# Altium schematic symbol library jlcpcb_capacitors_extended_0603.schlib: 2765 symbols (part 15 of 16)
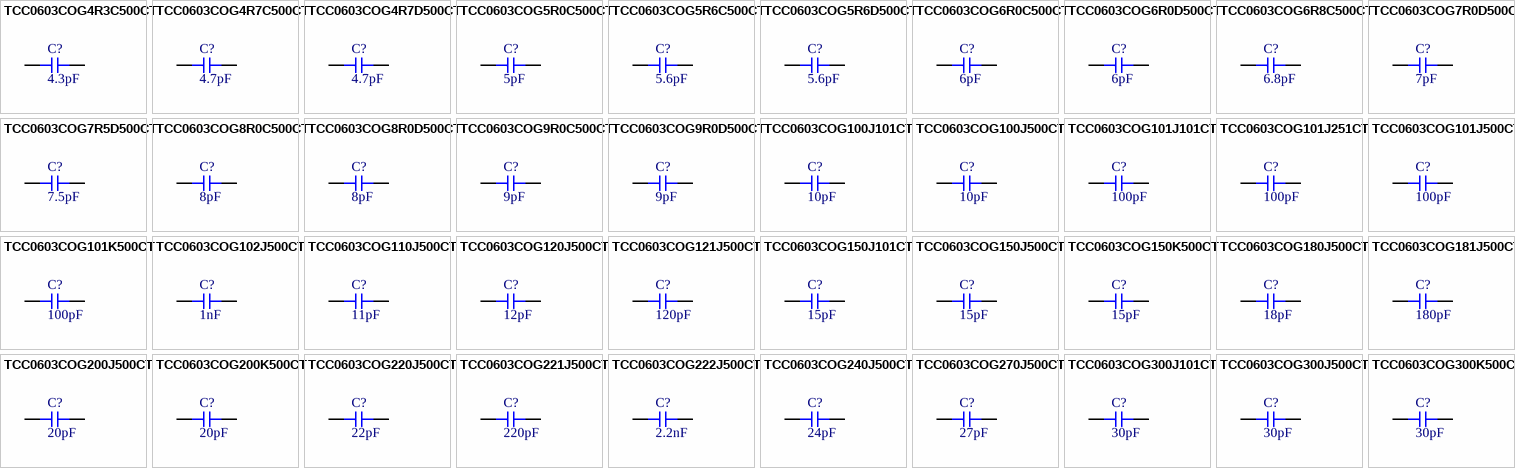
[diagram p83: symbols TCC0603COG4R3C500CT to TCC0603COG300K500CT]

## TCC0603COG4R7C500CT
designator C?  Capacitance: 4.7pF  (hidden comment: *)
Capacitor, Ceramic (MLCC), 4.7pF, ±0.25pF, 50V, C0G, ±0.25pF, SMD 0603; Manufacturer: CCTC; Manufacturer Part Number: TCC0603COG4R7C500CT
footprint CAP-0603 (0603 (1608M) Capacitor)
pins: 1, 2

## TCC0603COG4R7D500CT
designator C?  Capacitance: 4.7pF  (hidden comment: *)
Capacitor, Ceramic (MLCC), 4.7pF, ±0.5pF, 50V, C0G, ±0.5pF, SMD 0603; Manufacturer: CCTC; Manufacturer Part Number: TCC0603COG4R7D500CT
footprint CAP-0603 (0603 (1608M) Capacitor)
pins: 1, 2

## TCC0603COG5R0C500CT
designator C?  Capacitance: 5pF  (hidden comment: *)
Capacitor, Ceramic (MLCC), 5pF, ±0.25pF, 50V, C0G, ±0.25pF, SMD 0603; Manufacturer: CCTC; Manufacturer Part Number: TCC0603COG5R0C500CT
footprint CAP-0603 (0603 (1608M) Capacitor)
pins: 1, 2

## TCC0603COG5R6C500CT
designator C?  Capacitance: 5.6pF  (hidden comment: *)
Capacitor, Ceramic (MLCC), 5.6pF, ±0.25pF, 50V, C0G, ±0.25pF, SMD 0603; Manufacturer: CCTC; Manufacturer Part Number: TCC0603COG5R6C500CT
footprint CAP-0603 (0603 (1608M) Capacitor)
pins: 1, 2

## TCC0603COG5R6D500CT
designator C?  Capacitance: 5.6pF  (hidden comment: *)
Capacitor, Ceramic (MLCC), 5.6pF, ±0.5pF, 50V, C0G, ±0.5pF, SMD 0603; Manufacturer: CCTC; Manufacturer Part Number: TCC0603COG5R6D500CT
footprint CAP-0603 (0603 (1608M) Capacitor)
pins: 1, 2

## TCC0603COG6R0C500CT
designator C?  Capacitance: 6pF  (hidden comment: *)
Capacitor, Ceramic (MLCC), 6pF, ±0.25pF, 50V, C0G, ±0.25pF, SMD 0603; Manufacturer: CCTC; Manufacturer Part Number: TCC0603COG6R0C500CT
footprint CAP-0603 (0603 (1608M) Capacitor)
pins: 1, 2

## TCC0603COG6R0D500CT
designator C?  Capacitance: 6pF  (hidden comment: *)
Capacitor, Ceramic (MLCC), 6pF, ±0.5pF, 50V, C0G, ±0.5pF, SMD 0603; Manufacturer: CCTC; Manufacturer Part Number: TCC0603COG6R0D500CT
footprint CAP-0603 (0603 (1608M) Capacitor)
pins: 1, 2

## TCC0603COG6R8C500CT
designator C?  Capacitance: 6.8pF  (hidden comment: *)
Capacitor, Ceramic (MLCC), 6.8pF, ±0.25pF, 50V, C0G, ±0.25pF, SMD 0603; Manufacturer: CCTC; Manufacturer Part Number: TCC0603COG6R8C500CT
footprint CAP-0603 (0603 (1608M) Capacitor)
pins: 1, 2

## TCC0603COG7R0D500CT
designator C?  Capacitance: 7pF  (hidden comment: *)
Capacitor, Ceramic (MLCC), 7pF, ±0.5pF, 50V, C0G, ±0.5pF, SMD 0603; Manufacturer: CCTC; Manufacturer Part Number: TCC0603COG7R0D500CT
footprint CAP-0603 (0603 (1608M) Capacitor)
pins: 1, 2

## TCC0603COG7R5D500CT
designator C?  Capacitance: 7.5pF  (hidden comment: *)
Capacitor, Ceramic (MLCC), 7.5pF, ±0.5pF, 50V, C0G, ±0.5pF, SMD 0603; Manufacturer: CCTC; Manufacturer Part Number: TCC0603COG7R5D500CT
footprint CAP-0603 (0603 (1608M) Capacitor)
pins: 1, 2

## TCC0603COG8R0C500CT
designator C?  Capacitance: 8pF  (hidden comment: *)
Capacitor, Ceramic (MLCC), 8pF, ±0.25pF, 50V, C0G, ±0.25pF, SMD 0603; Manufacturer: CCTC; Manufacturer Part Number: TCC0603COG8R0C500CT
footprint CAP-0603 (0603 (1608M) Capacitor)
pins: 1, 2

## TCC0603COG8R0D500CT
designator C?  Capacitance: 8pF  (hidden comment: *)
Capacitor, Ceramic (MLCC), 8pF, ±0.5pF, 50V, C0G, ±0.5pF, SMD 0603; Manufacturer: CCTC; Manufacturer Part Number: TCC0603COG8R0D500CT
footprint CAP-0603 (0603 (1608M) Capacitor)
pins: 1, 2

## TCC0603COG9R0C500CT
designator C?  Capacitance: 9pF  (hidden comment: *)
Capacitor, Ceramic (MLCC), 9pF, ±0.25pF, 50V, C0G, ±0.25pF, SMD 0603; Manufacturer: CCTC; Manufacturer Part Number: TCC0603COG9R0C500CT
footprint CAP-0603 (0603 (1608M) Capacitor)
pins: 1, 2

## TCC0603COG9R0D500CT
designator C?  Capacitance: 9pF  (hidden comment: *)
Capacitor, Ceramic (MLCC), 9pF, ±0.5pF, 50V, C0G, ±0.5pF, SMD 0603; Manufacturer: CCTC; Manufacturer Part Number: TCC0603COG9R0D500CT
footprint CAP-0603 (0603 (1608M) Capacitor)
pins: 1, 2

## TCC0603COG100J101CT
designator C?  Capacitance: 10pF  (hidden comment: *)
Capacitor, Ceramic (MLCC), 10pF, ±5%, 100V, C0G, ±5%, SMD 0603; Manufacturer: CCTC; Manufacturer Part Number: TCC0603COG100J101CT
footprint CAP-0603 (0603 (1608M) Capacitor)
pins: 1, 2

## TCC0603COG100J500CT
designator C?  Capacitance: 10pF  (hidden comment: *)
Capacitor, Ceramic (MLCC), 10pF, ±5%, 50V, C0G, ±5%, SMD 0603; Manufacturer: CCTC; Manufacturer Part Number: TCC0603COG100J500CT
footprint CAP-0603 (0603 (1608M) Capacitor)
pins: 1, 2

## TCC0603COG101J101CT
designator C?  Capacitance: 100pF  (hidden comment: *)
Capacitor, Ceramic (MLCC), 100pF, ±5%, 100V, C0G, ±5%, SMD 0603; Manufacturer: CCTC; Manufacturer Part Number: TCC0603COG101J101CT
footprint CAP-0603 (0603 (1608M) Capacitor)
pins: 1, 2

## TCC0603COG101J251CT
designator C?  Capacitance: 100pF  (hidden comment: *)
Capacitor, Ceramic (MLCC), 100pF, ±5%, 250V, C0G, ±5%, SMD 0603; Manufacturer: CCTC; Manufacturer Part Number: TCC0603COG101J251CT
footprint CAP-0603 (0603 (1608M) Capacitor)
pins: 1, 2

## TCC0603COG101J500CT
designator C?  Capacitance: 100pF  (hidden comment: *)
Capacitor, Ceramic (MLCC), 100pF, ±5%, 50V, C0G, ±5%, SMD 0603; Manufacturer: CCTC; Manufacturer Part Number: TCC0603COG101J500CT
footprint CAP-0603 (0603 (1608M) Capacitor)
pins: 1, 2

## TCC0603COG101K500CT
designator C?  Capacitance: 100pF  (hidden comment: *)
Capacitor, Ceramic (MLCC), 100pF, ±10%, 50V, C0G, ±10%, SMD 0603; Manufacturer: CCTC; Manufacturer Part Number: TCC0603COG101K500CT
footprint CAP-0603 (0603 (1608M) Capacitor)
pins: 1, 2

## TCC0603COG102J500CT
designator C?  Capacitance: 1nF  (hidden comment: *)
Capacitor, Ceramic (MLCC), 1nF, ±5%, 50V, C0G, ±5%, SMD 0603; Manufacturer: CCTC; Manufacturer Part Number: TCC0603COG102J500CT
footprint CAP-0603 (0603 (1608M) Capacitor)
pins: 1, 2

## TCC0603COG110J500CT
designator C?  Capacitance: 11pF  (hidden comment: *)
Capacitor, Ceramic (MLCC), 11pF, ±5%, 50V, C0G, ±5%, SMD 0603; Manufacturer: CCTC; Manufacturer Part Number: TCC0603COG110J500CT
footprint CAP-0603 (0603 (1608M) Capacitor)
pins: 1, 2

## TCC0603COG120J500CT
designator C?  Capacitance: 12pF  (hidden comment: *)
Capacitor, Ceramic (MLCC), 12pF, ±5%, 50V, C0G, ±5%, SMD 0603; Manufacturer: CCTC; Manufacturer Part Number: TCC0603COG120J500CT
footprint CAP-0603 (0603 (1608M) Capacitor)
pins: 1, 2

## TCC0603COG121J500CT
designator C?  Capacitance: 120pF  (hidden comment: *)
Capacitor, Ceramic (MLCC), 120pF, ±5%, 50V, C0G, ±5%, SMD 0603; Manufacturer: CCTC; Manufacturer Part Number: TCC0603COG121J500CT
footprint CAP-0603 (0603 (1608M) Capacitor)
pins: 1, 2

## TCC0603COG150J101CT
designator C?  Capacitance: 15pF  (hidden comment: *)
Capacitor, Ceramic (MLCC), 15pF, ±5%, 100V, C0G, ±5%, SMD 0603; Manufacturer: CCTC; Manufacturer Part Number: TCC0603COG150J101CT
footprint CAP-0603 (0603 (1608M) Capacitor)
pins: 1, 2

## TCC0603COG150J500CT
designator C?  Capacitance: 15pF  (hidden comment: *)
Capacitor, Ceramic (MLCC), 15pF, ±5%, 50V, C0G, ±5%, SMD 0603; Manufacturer: CCTC; Manufacturer Part Number: TCC0603COG150J500CT
footprint CAP-0603 (0603 (1608M) Capacitor)
pins: 1, 2

## TCC0603COG150K500CT
designator C?  Capacitance: 15pF  (hidden comment: *)
Capacitor, Ceramic (MLCC), 15pF, ±10%, 50V, C0G, ±10%, SMD 0603; Manufacturer: CCTC; Manufacturer Part Number: TCC0603COG150K500CT
footprint CAP-0603 (0603 (1608M) Capacitor)
pins: 1, 2

## TCC0603COG180J500CT
designator C?  Capacitance: 18pF  (hidden comment: *)
Capacitor, Ceramic (MLCC), 18pF, ±5%, 50V, C0G, ±5%, SMD 0603; Manufacturer: CCTC; Manufacturer Part Number: TCC0603COG180J500CT
footprint CAP-0603 (0603 (1608M) Capacitor)
pins: 1, 2

## TCC0603COG181J500CT
designator C?  Capacitance: 180pF  (hidden comment: *)
Capacitor, Ceramic (MLCC), 180pF, ±5%, 50V, C0G, ±5%, SMD 0603; Manufacturer: CCTC; Manufacturer Part Number: TCC0603COG181J500CT
footprint CAP-0603 (0603 (1608M) Capacitor)
pins: 1, 2

## TCC0603COG200J500CT
designator C?  Capacitance: 20pF  (hidden comment: *)
Capacitor, Ceramic (MLCC), 20pF, ±5%, 50V, C0G, ±5%, SMD 0603; Manufacturer: CCTC; Manufacturer Part Number: TCC0603COG200J500CT
footprint CAP-0603 (0603 (1608M) Capacitor)
pins: 1, 2

## TCC0603COG200K500CT
designator C?  Capacitance: 20pF  (hidden comment: *)
Capacitor, Ceramic (MLCC), 20pF, ±10%, 50V, C0G, ±10%, SMD 0603; Manufacturer: CCTC; Manufacturer Part Number: TCC0603COG200K500CT
footprint CAP-0603 (0603 (1608M) Capacitor)
pins: 1, 2

## TCC0603COG220J500CT
designator C?  Capacitance: 22pF  (hidden comment: *)
Capacitor, Ceramic (MLCC), 22pF, ±5%, 50V, C0G, ±5%, SMD 0603; Manufacturer: CCTC; Manufacturer Part Number: TCC0603COG220J500CT
footprint CAP-0603 (0603 (1608M) Capacitor)
pins: 1, 2

## TCC0603COG221J500CT
designator C?  Capacitance: 220pF  (hidden comment: *)
Capacitor, Ceramic (MLCC), 220pF, ±5%, 50V, C0G, ±5%, SMD 0603; Manufacturer: CCTC; Manufacturer Part Number: TCC0603COG221J500CT
footprint CAP-0603 (0603 (1608M) Capacitor)
pins: 1, 2

## TCC0603COG222J500CT
designator C?  Capacitance: 2.2nF  (hidden comment: *)
Capacitor, Ceramic (MLCC), 2.2nF, ±5%, 50V, C0G, ±5%, SMD 0603; Manufacturer: CCTC; Manufacturer Part Number: TCC0603COG222J500CT
footprint CAP-0603 (0603 (1608M) Capacitor)
pins: 1, 2

## TCC0603COG240J500CT
designator C?  Capacitance: 24pF  (hidden comment: *)
Capacitor, Ceramic (MLCC), 24pF, ±5%, 50V, C0G, ±5%, SMD 0603; Manufacturer: CCTC; Manufacturer Part Number: TCC0603COG240J500CT
footprint CAP-0603 (0603 (1608M) Capacitor)
pins: 1, 2

## TCC0603COG270J500CT
designator C?  Capacitance: 27pF  (hidden comment: *)
Capacitor, Ceramic (MLCC), 27pF, ±5%, 50V, C0G, ±5%, SMD 0603; Manufacturer: CCTC; Manufacturer Part Number: TCC0603COG270J500CT
footprint CAP-0603 (0603 (1608M) Capacitor)
pins: 1, 2

## TCC0603COG300J101CT
designator C?  Capacitance: 30pF  (hidden comment: *)
Capacitor, Ceramic (MLCC), 30pF, ±5%, 100V, C0G, ±5%, SMD 0603; Manufacturer: CCTC; Manufacturer Part Number: TCC0603COG300J101CT
footprint CAP-0603 (0603 (1608M) Capacitor)
pins: 1, 2

## TCC0603COG300J500CT
designator C?  Capacitance: 30pF  (hidden comment: *)
Capacitor, Ceramic (MLCC), 30pF, ±5%, 50V, C0G, ±5%, SMD 0603; Manufacturer: CCTC; Manufacturer Part Number: TCC0603COG300J500CT
footprint CAP-0603 (0603 (1608M) Capacitor)
pins: 1, 2

## TCC0603COG300K500CT
designator C?  Capacitance: 30pF  (hidden comment: *)
Capacitor, Ceramic (MLCC), 30pF, ±10%, 50V, C0G, ±10%, SMD 0603; Manufacturer: CCTC; Manufacturer Part Number: TCC0603COG300K500CT
footprint CAP-0603 (0603 (1608M) Capacitor)
pins: 1, 2

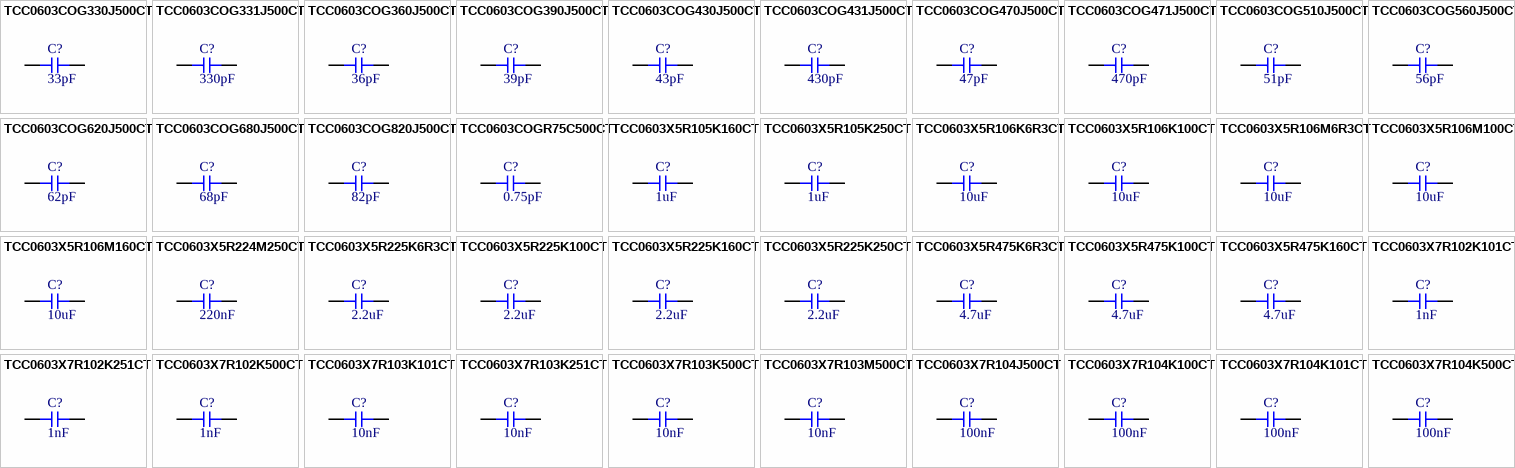
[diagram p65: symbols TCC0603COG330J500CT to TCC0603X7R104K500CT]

## TCC0603COG330J500CT
designator C?  Capacitance: 33pF  (hidden comment: *)
Capacitor, Ceramic (MLCC), 33pF, ±5%, 50V, C0G, ±5%, SMD 0603; Manufacturer: CCTC; Manufacturer Part Number: TCC0603COG330J500CT
footprint CAP-0603 (0603 (1608M) Capacitor)
pins: 1, 2

## TCC0603COG331J500CT
designator C?  Capacitance: 330pF  (hidden comment: *)
Capacitor, Ceramic (MLCC), 330pF, ±5%, 50V, C0G, ±5%, SMD 0603; Manufacturer: CCTC; Manufacturer Part Number: TCC0603COG331J500CT
footprint CAP-0603 (0603 (1608M) Capacitor)
pins: 1, 2

## TCC0603COG360J500CT
designator C?  Capacitance: 36pF  (hidden comment: *)
Capacitor, Ceramic (MLCC), 36pF, ±5%, 50V, C0G, ±5%, SMD 0603; Manufacturer: CCTC; Manufacturer Part Number: TCC0603COG360J500CT
footprint CAP-0603 (0603 (1608M) Capacitor)
pins: 1, 2

## TCC0603COG390J500CT
designator C?  Capacitance: 39pF  (hidden comment: *)
Capacitor, Ceramic (MLCC), 39pF, ±5%, 50V, C0G, ±5%, SMD 0603; Manufacturer: CCTC; Manufacturer Part Number: TCC0603COG390J500CT
footprint CAP-0603 (0603 (1608M) Capacitor)
pins: 1, 2

## TCC0603COG430J500CT
designator C?  Capacitance: 43pF  (hidden comment: *)
Capacitor, Ceramic (MLCC), 43pF, ±5%, 50V, C0G, ±5%, SMD 0603; Manufacturer: CCTC; Manufacturer Part Number: TCC0603COG430J500CT
footprint CAP-0603 (0603 (1608M) Capacitor)
pins: 1, 2

## TCC0603COG431J500CT
designator C?  Capacitance: 430pF  (hidden comment: *)
Capacitor, Ceramic (MLCC), 430pF, ±5%, 50V, C0G, ±5%, SMD 0603; Manufacturer: CCTC; Manufacturer Part Number: TCC0603COG431J500CT
footprint CAP-0603 (0603 (1608M) Capacitor)
pins: 1, 2

## TCC0603COG470J500CT
designator C?  Capacitance: 47pF  (hidden comment: *)
Capacitor, Ceramic (MLCC), 47pF, ±5%, 50V, C0G, ±5%, SMD 0603; Manufacturer: CCTC; Manufacturer Part Number: TCC0603COG470J500CT
footprint CAP-0603 (0603 (1608M) Capacitor)
pins: 1, 2

## TCC0603COG471J500CT
designator C?  Capacitance: 470pF  (hidden comment: *)
Capacitor, Ceramic (MLCC), 470pF, ±5%, 50V, C0G, ±5%, SMD 0603; Manufacturer: CCTC; Manufacturer Part Number: TCC0603COG471J500CT
footprint CAP-0603 (0603 (1608M) Capacitor)
pins: 1, 2

## TCC0603COG510J500CT
designator C?  Capacitance: 51pF  (hidden comment: *)
Capacitor, Ceramic (MLCC), 51pF, ±5%, 50V, C0G, ±5%, SMD 0603; Manufacturer: CCTC; Manufacturer Part Number: TCC0603COG510J500CT
footprint CAP-0603 (0603 (1608M) Capacitor)
pins: 1, 2

## TCC0603COG560J500CT
designator C?  Capacitance: 56pF  (hidden comment: *)
Capacitor, Ceramic (MLCC), 56pF, ±5%, 50V, C0G, ±5%, SMD 0603; Manufacturer: CCTC; Manufacturer Part Number: TCC0603COG560J500CT
footprint CAP-0603 (0603 (1608M) Capacitor)
pins: 1, 2

## TCC0603COG620J500CT
designator C?  Capacitance: 62pF  (hidden comment: *)
Capacitor, Ceramic (MLCC), 62pF, ±5%, 50V, C0G, ±5%, SMD 0603; Manufacturer: CCTC; Manufacturer Part Number: TCC0603COG620J500CT
footprint CAP-0603 (0603 (1608M) Capacitor)
pins: 1, 2

## TCC0603COG680J500CT
designator C?  Capacitance: 68pF  (hidden comment: *)
Capacitor, Ceramic (MLCC), 68pF, ±5%, 50V, C0G, ±5%, SMD 0603; Manufacturer: CCTC; Manufacturer Part Number: TCC0603COG680J500CT
footprint CAP-0603 (0603 (1608M) Capacitor)
pins: 1, 2

## TCC0603COG820J500CT
designator C?  Capacitance: 82pF  (hidden comment: *)
Capacitor, Ceramic (MLCC), 82pF, ±5%, 50V, C0G, ±5%, SMD 0603; Manufacturer: CCTC; Manufacturer Part Number: TCC0603COG820J500CT
footprint CAP-0603 (0603 (1608M) Capacitor)
pins: 1, 2

## TCC0603COGR75C500CT
designator C?  Capacitance: 0.75pF  (hidden comment: *)
Capacitor, Ceramic (MLCC), 0.75pF, ±0.25pF, 50V, C0G, ±0.25pF, SMD 0603; Manufacturer: CCTC; Manufacturer Part Number: TCC0603COGR75C500CT
footprint CAP-0603 (0603 (1608M) Capacitor)
pins: 1, 2

## TCC0603X5R105K160CT
designator C?  Capacitance: 1uF  (hidden comment: *)
Capacitor, Ceramic (MLCC), 1uF, ±10%, 16V, X5R, ±10%, SMD 0603; Manufacturer: CCTC; Manufacturer Part Number: TCC0603X5R105K160CT
footprint CAP-0603 (0603 (1608M) Capacitor)
pins: 1, 2

## TCC0603X5R105K250CT
designator C?  Capacitance: 1uF  (hidden comment: *)
Capacitor, Ceramic (MLCC), 1uF, ±10%, 25V, X5R, ±10%, SMD 0603; Manufacturer: CCTC; Manufacturer Part Number: TCC0603X5R105K250CT
footprint CAP-0603 (0603 (1608M) Capacitor)
pins: 1, 2

## TCC0603X5R106K6R3CT
designator C?  Capacitance: 10uF  (hidden comment: *)
Capacitor, Ceramic (MLCC), 10uF, ±10%, 6.3V, X5R, ±10%, SMD 0603; Manufacturer: CCTC; Manufacturer Part Number: TCC0603X5R106K6R3CT
footprint CAP-0603 (0603 (1608M) Capacitor)
pins: 1, 2

## TCC0603X5R106K100CT
designator C?  Capacitance: 10uF  (hidden comment: *)
Capacitor, Ceramic (MLCC), 10uF, ±10%, 10V, X5R, ±10%, SMD 0603; Manufacturer: CCTC; Manufacturer Part Number: TCC0603X5R106K100CT
footprint CAP-0603 (0603 (1608M) Capacitor)
pins: 1, 2

## TCC0603X5R106M6R3CT
designator C?  Capacitance: 10uF  (hidden comment: *)
Capacitor, Ceramic (MLCC), 10uF, ±20%, 6.3V, X5R, ±20%, SMD 0603; Manufacturer: CCTC; Manufacturer Part Number: TCC0603X5R106M6R3CT
footprint CAP-0603 (0603 (1608M) Capacitor)
pins: 1, 2

## TCC0603X5R106M100CT
designator C?  Capacitance: 10uF  (hidden comment: *)
Capacitor, Ceramic (MLCC), 10uF, ±20%, 10V, X5R, ±20%, SMD 0603; Manufacturer: CCTC; Manufacturer Part Number: TCC0603X5R106M100CT
footprint CAP-0603 (0603 (1608M) Capacitor)
pins: 1, 2

## TCC0603X5R106M160CT
designator C?  Capacitance: 10uF  (hidden comment: *)
Capacitor, Ceramic (MLCC), 10uF, ±20%, 16V, X5R, ±20%, SMD 0603; Manufacturer: CCTC; Manufacturer Part Number: TCC0603X5R106M160CT
footprint CAP-0603 (0603 (1608M) Capacitor)
pins: 1, 2

## TCC0603X5R224M250CT
designator C?  Capacitance: 220nF  (hidden comment: *)
Capacitor, Ceramic (MLCC), 220nF, ±20%, 25V, X5R, ±20%, SMD 0603; Manufacturer: CCTC; Manufacturer Part Number: TCC0603X5R224M250CT
footprint CAP-0603 (0603 (1608M) Capacitor)
pins: 1, 2

## TCC0603X5R225K6R3CT
designator C?  Capacitance: 2.2uF  (hidden comment: *)
Capacitor, Ceramic (MLCC), 2.2uF, ±10%, 6.3V, X5R, ±10%, SMD 0603; Manufacturer: CCTC; Manufacturer Part Number: TCC0603X5R225K6R3CT
footprint CAP-0603 (0603 (1608M) Capacitor)
pins: 1, 2

## TCC0603X5R225K100CT
designator C?  Capacitance: 2.2uF  (hidden comment: *)
Capacitor, Ceramic (MLCC), 2.2uF, ±10%, 10V, X5R, ±10%, SMD 0603; Manufacturer: CCTC; Manufacturer Part Number: TCC0603X5R225K100CT
footprint CAP-0603 (0603 (1608M) Capacitor)
pins: 1, 2

## TCC0603X5R225K160CT
designator C?  Capacitance: 2.2uF  (hidden comment: *)
Capacitor, Ceramic (MLCC), 2.2uF, ±10%, 16V, X5R, ±10%, SMD 0603; Manufacturer: CCTC; Manufacturer Part Number: TCC0603X5R225K160CT
footprint CAP-0603 (0603 (1608M) Capacitor)
pins: 1, 2

## TCC0603X5R225K250CT
designator C?  Capacitance: 2.2uF  (hidden comment: *)
Capacitor, Ceramic (MLCC), 2.2uF, ±10%, 25V, X5R, ±10%, SMD 0603; Manufacturer: CCTC; Manufacturer Part Number: TCC0603X5R225K250CT
footprint CAP-0603 (0603 (1608M) Capacitor)
pins: 1, 2

## TCC0603X5R475K6R3CT
designator C?  Capacitance: 4.7uF  (hidden comment: *)
Capacitor, Ceramic (MLCC), 4.7uF, ±10%, 6.3V, X5R, ±10%, SMD 0603; Manufacturer: CCTC; Manufacturer Part Number: TCC0603X5R475K6R3CT
footprint CAP-0603 (0603 (1608M) Capacitor)
pins: 1, 2

## TCC0603X5R475K100CT
designator C?  Capacitance: 4.7uF  (hidden comment: *)
Capacitor, Ceramic (MLCC), 4.7uF, ±10%, 10V, X5R, ±10%, SMD 0603; Manufacturer: CCTC; Manufacturer Part Number: TCC0603X5R475K100CT
footprint CAP-0603 (0603 (1608M) Capacitor)
pins: 1, 2

## TCC0603X5R475K160CT
designator C?  Capacitance: 4.7uF  (hidden comment: *)
Capacitor, Ceramic (MLCC), 4.7uF, ±10%, 16V, X5R, ±10%, SMD 0603; Manufacturer: CCTC; Manufacturer Part Number: TCC0603X5R475K160CT
footprint CAP-0603 (0603 (1608M) Capacitor)
pins: 1, 2

## TCC0603X7R102K101CT
designator C?  Capacitance: 1nF  (hidden comment: *)
Capacitor, Ceramic (MLCC), 1nF, ±10%, 100V, X7R, ±10%, SMD 0603; Manufacturer: CCTC; Manufacturer Part Number: TCC0603X7R102K101CT
footprint CAP-0603 (0603 (1608M) Capacitor)
pins: 1, 2

## TCC0603X7R102K251CT
designator C?  Capacitance: 1nF  (hidden comment: *)
Capacitor, Ceramic (MLCC), 1nF, ±10%, 250V, X7R, ±10%, SMD 0603; Manufacturer: CCTC; Manufacturer Part Number: TCC0603X7R102K251CT
footprint CAP-0603 (0603 (1608M) Capacitor)
pins: 1, 2

## TCC0603X7R102K500CT
designator C?  Capacitance: 1nF  (hidden comment: *)
Capacitor, Ceramic (MLCC), 1nF, ±10%, 50V, X7R, ±10%, SMD 0603; Manufacturer: CCTC; Manufacturer Part Number: TCC0603X7R102K500CT
footprint CAP-0603 (0603 (1608M) Capacitor)
pins: 1, 2

## TCC0603X7R103K101CT
designator C?  Capacitance: 10nF  (hidden comment: *)
Capacitor, Ceramic (MLCC), 10nF, ±10%, 100V, X7R, ±10%, SMD 0603; Manufacturer: CCTC; Manufacturer Part Number: TCC0603X7R103K101CT
footprint CAP-0603 (0603 (1608M) Capacitor)
pins: 1, 2

## TCC0603X7R103K251CT
designator C?  Capacitance: 10nF  (hidden comment: *)
Capacitor, Ceramic (MLCC), 10nF, ±10%, 250V, X7R, ±10%, SMD 0603; Manufacturer: CCTC; Manufacturer Part Number: TCC0603X7R103K251CT
footprint CAP-0603 (0603 (1608M) Capacitor)
pins: 1, 2

## TCC0603X7R103K500CT
designator C?  Capacitance: 10nF  (hidden comment: *)
Capacitor, Ceramic (MLCC), 10nF, ±10%, 50V, X7R, ±10%, SMD 0603; Manufacturer: CCTC; Manufacturer Part Number: TCC0603X7R103K500CT
footprint CAP-0603 (0603 (1608M) Capacitor)
pins: 1, 2

## TCC0603X7R103M500CT
designator C?  Capacitance: 10nF  (hidden comment: *)
Capacitor, Ceramic (MLCC), 10nF, ±20%, 50V, X7R, ±20%, SMD 0603; Manufacturer: CCTC; Manufacturer Part Number: TCC0603X7R103M500CT
footprint CAP-0603 (0603 (1608M) Capacitor)
pins: 1, 2

## TCC0603X7R104J500CT
designator C?  Capacitance: 100nF  (hidden comment: *)
Capacitor, Ceramic (MLCC), 100nF, ±5%, 50V, X7R, ±5%, SMD 0603; Manufacturer: CCTC; Manufacturer Part Number: TCC0603X7R104J500CT
footprint CAP-0603 (0603 (1608M) Capacitor)
pins: 1, 2

## TCC0603X7R104K100CT
designator C?  Capacitance: 100nF  (hidden comment: *)
Capacitor, Ceramic (MLCC), 100nF, ±10%, 10V, X7R, ±10%, SMD 0603; Manufacturer: CCTC; Manufacturer Part Number: TCC0603X7R104K100CT
footprint CAP-0603 (0603 (1608M) Capacitor)
pins: 1, 2

## TCC0603X7R104K101CT
designator C?  Capacitance: 100nF  (hidden comment: *)
Capacitor, Ceramic (MLCC), 100nF, ±10%, 100V, X7R, ±10%, SMD 0603; Manufacturer: CCTC; Manufacturer Part Number: TCC0603X7R104K101CT
footprint CAP-0603 (0603 (1608M) Capacitor)
pins: 1, 2

## TCC0603X7R104K500CT
designator C?  Capacitance: 100nF  (hidden comment: *)
Capacitor, Ceramic (MLCC), 100nF, ±10%, 50V, X7R, ±10%, SMD 0603; Manufacturer: CCTC; Manufacturer Part Number: TCC0603X7R104K500CT
footprint CAP-0603 (0603 (1608M) Capacitor)
pins: 1, 2

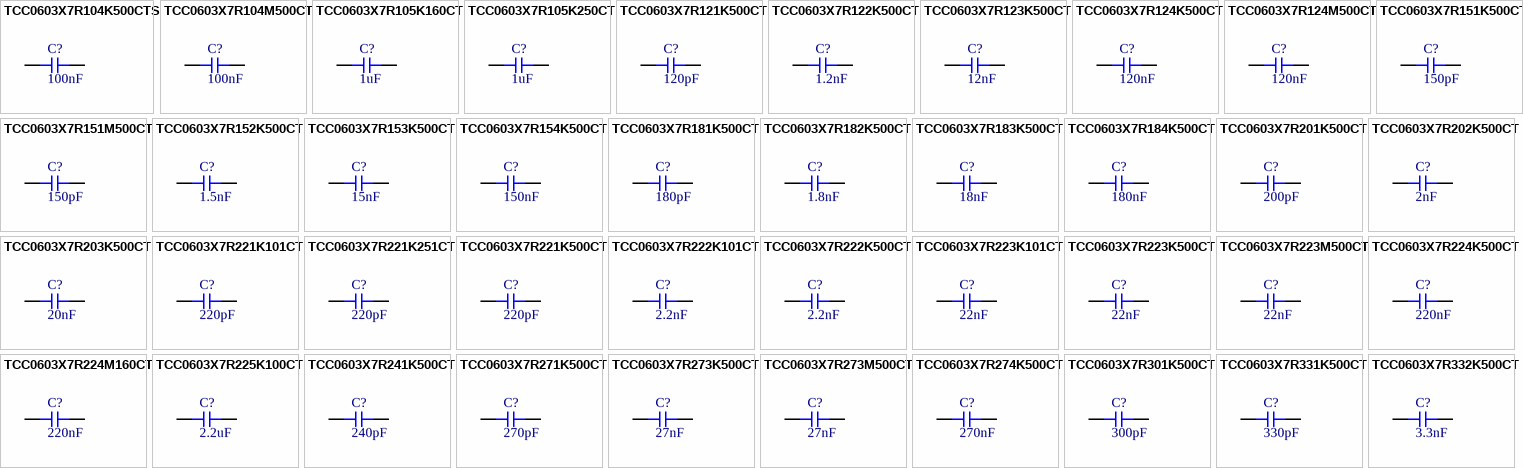
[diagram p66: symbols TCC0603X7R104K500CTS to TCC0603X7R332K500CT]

## TCC0603X7R104K500CTS
designator C?  Capacitance: 100nF  (hidden comment: *)
Capacitor, Ceramic (MLCC), 100nF, ±10%, 50V, X7R, ±10%, SMD 0603; Manufacturer: CCTC; Manufacturer Part Number: TCC0603X7R104K500CTS
footprint CAP-0603 (0603 (1608M) Capacitor)
pins: 1, 2

## TCC0603X7R104M500CT
designator C?  Capacitance: 100nF  (hidden comment: *)
Capacitor, Ceramic (MLCC), 100nF, ±20%, 50V, X7R, ±20%, SMD 0603; Manufacturer: CCTC; Manufacturer Part Number: TCC0603X7R104M500CT
footprint CAP-0603 (0603 (1608M) Capacitor)
pins: 1, 2

## TCC0603X7R105K160CT
designator C?  Capacitance: 1uF  (hidden comment: *)
Capacitor, Ceramic (MLCC), 1uF, ±10%, 16V, X7R, ±10%, SMD 0603; Manufacturer: CCTC; Manufacturer Part Number: TCC0603X7R105K160CT
footprint CAP-0603 (0603 (1608M) Capacitor)
pins: 1, 2

## TCC0603X7R105K250CT
designator C?  Capacitance: 1uF  (hidden comment: *)
Capacitor, Ceramic (MLCC), 1uF, ±10%, 25V, X7R, ±10%, SMD 0603; Manufacturer: CCTC; Manufacturer Part Number: TCC0603X7R105K250CT
footprint CAP-0603 (0603 (1608M) Capacitor)
pins: 1, 2

## TCC0603X7R121K500CT
designator C?  Capacitance: 120pF  (hidden comment: *)
Capacitor, Ceramic (MLCC), 120pF, ±10%, 50V, X7R, ±10%, SMD 0603; Manufacturer: CCTC; Manufacturer Part Number: TCC0603X7R121K500CT
footprint CAP-0603 (0603 (1608M) Capacitor)
pins: 1, 2

## TCC0603X7R122K500CT
designator C?  Capacitance: 1.2nF  (hidden comment: *)
Capacitor, Ceramic (MLCC), 1.2nF, ±10%, 50V, X7R, ±10%, SMD 0603; Manufacturer: CCTC; Manufacturer Part Number: TCC0603X7R122K500CT
footprint CAP-0603 (0603 (1608M) Capacitor)
pins: 1, 2

## TCC0603X7R123K500CT
designator C?  Capacitance: 12nF  (hidden comment: *)
Capacitor, Ceramic (MLCC), 12nF, ±10%, 50V, X7R, ±10%, SMD 0603; Manufacturer: CCTC; Manufacturer Part Number: TCC0603X7R123K500CT
footprint CAP-0603 (0603 (1608M) Capacitor)
pins: 1, 2

## TCC0603X7R124K500CT
designator C?  Capacitance: 120nF  (hidden comment: *)
Capacitor, Ceramic (MLCC), 120nF, ±10%, 50V, X7R, ±10%, SMD 0603; Manufacturer: CCTC; Manufacturer Part Number: TCC0603X7R124K500CT
footprint CAP-0603 (0603 (1608M) Capacitor)
pins: 1, 2

## TCC0603X7R124M500CT
designator C?  Capacitance: 120nF  (hidden comment: *)
Capacitor, Ceramic (MLCC), 120nF, ±20%, 50V, X7R, ±20%, SMD 0603; Manufacturer: CCTC; Manufacturer Part Number: TCC0603X7R124M500CT
footprint CAP-0603 (0603 (1608M) Capacitor)
pins: 1, 2

## TCC0603X7R151K500CT
designator C?  Capacitance: 150pF  (hidden comment: *)
Capacitor, Ceramic (MLCC), 150pF, ±10%, 50V, X7R, ±10%, SMD 0603; Manufacturer: CCTC; Manufacturer Part Number: TCC0603X7R151K500CT
footprint CAP-0603 (0603 (1608M) Capacitor)
pins: 1, 2

## TCC0603X7R151M500CT
designator C?  Capacitance: 150pF  (hidden comment: *)
Capacitor, Ceramic (MLCC), 150pF, ±20%, 50V, X7R, ±20%, SMD 0603; Manufacturer: CCTC; Manufacturer Part Number: TCC0603X7R151M500CT
footprint CAP-0603 (0603 (1608M) Capacitor)
pins: 1, 2

## TCC0603X7R152K500CT
designator C?  Capacitance: 1.5nF  (hidden comment: *)
Capacitor, Ceramic (MLCC), 1.5nF, ±10%, 50V, X7R, ±10%, SMD 0603; Manufacturer: CCTC; Manufacturer Part Number: TCC0603X7R152K500CT
footprint CAP-0603 (0603 (1608M) Capacitor)
pins: 1, 2

## TCC0603X7R153K500CT
designator C?  Capacitance: 15nF  (hidden comment: *)
Capacitor, Ceramic (MLCC), 15nF, ±10%, 50V, X7R, ±10%, SMD 0603; Manufacturer: CCTC; Manufacturer Part Number: TCC0603X7R153K500CT
footprint CAP-0603 (0603 (1608M) Capacitor)
pins: 1, 2

## TCC0603X7R154K500CT
designator C?  Capacitance: 150nF  (hidden comment: *)
Capacitor, Ceramic (MLCC), 150nF, ±10%, 50V, X7R, ±10%, SMD 0603; Manufacturer: CCTC; Manufacturer Part Number: TCC0603X7R154K500CT
footprint CAP-0603 (0603 (1608M) Capacitor)
pins: 1, 2

## TCC0603X7R181K500CT
designator C?  Capacitance: 180pF  (hidden comment: *)
Capacitor, Ceramic (MLCC), 180pF, ±10%, 50V, X7R, ±10%, SMD 0603; Manufacturer: CCTC; Manufacturer Part Number: TCC0603X7R181K500CT
footprint CAP-0603 (0603 (1608M) Capacitor)
pins: 1, 2

## TCC0603X7R182K500CT
designator C?  Capacitance: 1.8nF  (hidden comment: *)
Capacitor, Ceramic (MLCC), 1.8nF, ±10%, 50V, X7R, ±10%, SMD 0603; Manufacturer: CCTC; Manufacturer Part Number: TCC0603X7R182K500CT
footprint CAP-0603 (0603 (1608M) Capacitor)
pins: 1, 2

## TCC0603X7R183K500CT
designator C?  Capacitance: 18nF  (hidden comment: *)
Capacitor, Ceramic (MLCC), 18nF, ±10%, 50V, X7R, ±10%, SMD 0603; Manufacturer: CCTC; Manufacturer Part Number: TCC0603X7R183K500CT
footprint CAP-0603 (0603 (1608M) Capacitor)
pins: 1, 2

## TCC0603X7R184K500CT
designator C?  Capacitance: 180nF  (hidden comment: *)
Capacitor, Ceramic (MLCC), 180nF, ±10%, 50V, ±10%, SMD 0603; Manufacturer: CCTC; Manufacturer Part Number: TCC0603X7R184K500CT
footprint CAP-0603 (0603 (1608M) Capacitor)
pins: 1, 2

## TCC0603X7R201K500CT
designator C?  Capacitance: 200pF  (hidden comment: *)
Capacitor, Ceramic (MLCC), 200pF, ±10%, 50V, X7R, ±10%, SMD 0603; Manufacturer: CCTC; Manufacturer Part Number: TCC0603X7R201K500CT
footprint CAP-0603 (0603 (1608M) Capacitor)
pins: 1, 2

## TCC0603X7R202K500CT
designator C?  Capacitance: 2nF  (hidden comment: *)
Capacitor, Ceramic (MLCC), 2nF, ±10%, 50V, X7R, ±10%, SMD 0603; Manufacturer: CCTC; Manufacturer Part Number: TCC0603X7R202K500CT
footprint CAP-0603 (0603 (1608M) Capacitor)
pins: 1, 2

## TCC0603X7R203K500CT
designator C?  Capacitance: 20nF  (hidden comment: *)
Capacitor, Ceramic (MLCC), 20nF, ±10%, 50V, X7R, ±10%, SMD 0603; Manufacturer: CCTC; Manufacturer Part Number: TCC0603X7R203K500CT
footprint CAP-0603 (0603 (1608M) Capacitor)
pins: 1, 2

## TCC0603X7R221K101CT
designator C?  Capacitance: 220pF  (hidden comment: *)
Capacitor, Ceramic (MLCC), 220pF, ±10%, 100V, X7R, ±10%, SMD 0603; Manufacturer: CCTC; Manufacturer Part Number: TCC0603X7R221K101CT
footprint CAP-0603 (0603 (1608M) Capacitor)
pins: 1, 2

## TCC0603X7R221K251CT
designator C?  Capacitance: 220pF  (hidden comment: *)
Capacitor, Ceramic (MLCC), 220pF, ±10%, 250V, X7R, ±10%, SMD 0603; Manufacturer: CCTC; Manufacturer Part Number: TCC0603X7R221K251CT
footprint CAP-0603 (0603 (1608M) Capacitor)
pins: 1, 2

## TCC0603X7R221K500CT
designator C?  Capacitance: 220pF  (hidden comment: *)
Capacitor, Ceramic (MLCC), 220pF, ±10%, 50V, X7R, ±10%, SMD 0603; Manufacturer: CCTC; Manufacturer Part Number: TCC0603X7R221K500CT
footprint CAP-0603 (0603 (1608M) Capacitor)
pins: 1, 2

## TCC0603X7R222K101CT
designator C?  Capacitance: 2.2nF  (hidden comment: *)
Capacitor, Ceramic (MLCC), 2.2nF, ±10%, 100V, X7R, ±10%, SMD 0603; Manufacturer: CCTC; Manufacturer Part Number: TCC0603X7R222K101CT
footprint CAP-0603 (0603 (1608M) Capacitor)
pins: 1, 2

## TCC0603X7R222K500CT
designator C?  Capacitance: 2.2nF  (hidden comment: *)
Capacitor, Ceramic (MLCC), 2.2nF, ±10%, 50V, X7R, ±10%, SMD 0603; Manufacturer: CCTC; Manufacturer Part Number: TCC0603X7R222K500CT
footprint CAP-0603 (0603 (1608M) Capacitor)
pins: 1, 2

## TCC0603X7R223K101CT
designator C?  Capacitance: 22nF  (hidden comment: *)
Capacitor, Ceramic (MLCC), 22nF, ±10%, 100V, X7R, ±10%, SMD 0603; Manufacturer: CCTC; Manufacturer Part Number: TCC0603X7R223K101CT
footprint CAP-0603 (0603 (1608M) Capacitor)
pins: 1, 2

## TCC0603X7R223K500CT
designator C?  Capacitance: 22nF  (hidden comment: *)
Capacitor, Ceramic (MLCC), 22nF, ±10%, 50V, X7R, ±10%, SMD 0603; Manufacturer: CCTC; Manufacturer Part Number: TCC0603X7R223K500CT
footprint CAP-0603 (0603 (1608M) Capacitor)
pins: 1, 2

## TCC0603X7R223M500CT
designator C?  Capacitance: 22nF  (hidden comment: *)
Capacitor, Ceramic (MLCC), 22nF, ±20%, 50V, X7R, ±20%, SMD 0603; Manufacturer: CCTC; Manufacturer Part Number: TCC0603X7R223M500CT
footprint CAP-0603 (0603 (1608M) Capacitor)
pins: 1, 2

## TCC0603X7R224K500CT
designator C?  Capacitance: 220nF  (hidden comment: *)
Capacitor, Ceramic (MLCC), 220nF, ±10%, 50V, X7R, ±10%, SMD 0603; Manufacturer: CCTC; Manufacturer Part Number: TCC0603X7R224K500CT
footprint CAP-0603 (0603 (1608M) Capacitor)
pins: 1, 2

## TCC0603X7R224M160CT
designator C?  Capacitance: 220nF  (hidden comment: *)
Capacitor, Ceramic (MLCC), 220nF, ±20%, 16V, X7R, ±20%, SMD 0603; Manufacturer: CCTC; Manufacturer Part Number: TCC0603X7R224M160CT
footprint CAP-0603 (0603 (1608M) Capacitor)
pins: 1, 2

## TCC0603X7R225K100CT
designator C?  Capacitance: 2.2uF  (hidden comment: *)
Capacitor, Ceramic (MLCC), 2.2uF, ±10%, 10V, X7R, ±10%, SMD 0603; Manufacturer: CCTC; Manufacturer Part Number: TCC0603X7R225K100CT
footprint CAP-0603 (0603 (1608M) Capacitor)
pins: 1, 2

## TCC0603X7R241K500CT
designator C?  Capacitance: 240pF  (hidden comment: *)
Capacitor, Ceramic (MLCC), 240pF, ±10%, 50V, X7R, ±10%, SMD 0603; Manufacturer: CCTC; Manufacturer Part Number: TCC0603X7R241K500CT
footprint CAP-0603 (0603 (1608M) Capacitor)
pins: 1, 2

## TCC0603X7R271K500CT
designator C?  Capacitance: 270pF  (hidden comment: *)
Capacitor, Ceramic (MLCC), 270pF, ±10%, 50V, X7R, ±10%, SMD 0603; Manufacturer: CCTC; Manufacturer Part Number: TCC0603X7R271K500CT
footprint CAP-0603 (0603 (1608M) Capacitor)
pins: 1, 2

## TCC0603X7R273K500CT
designator C?  Capacitance: 27nF  (hidden comment: *)
Capacitor, Ceramic (MLCC), 27nF, ±10%, 50V, X7R, ±10%, SMD 0603; Manufacturer: CCTC; Manufacturer Part Number: TCC0603X7R273K500CT
footprint CAP-0603 (0603 (1608M) Capacitor)
pins: 1, 2

## TCC0603X7R273M500CT
designator C?  Capacitance: 27nF  (hidden comment: *)
Capacitor, Ceramic (MLCC), 27nF, ±10%, 50V, X7R, ±10%, SMD 0603; Manufacturer: CCTC; Manufacturer Part Number: TCC0603X7R273M500CT
footprint CAP-0603 (0603 (1608M) Capacitor)
pins: 1, 2

## TCC0603X7R274K500CT
designator C?  Capacitance: 270nF  (hidden comment: *)
Capacitor, Ceramic (MLCC), 270nF, ±10%, 50V, X7R, ±10%, SMD 0603; Manufacturer: CCTC; Manufacturer Part Number: TCC0603X7R274K500CT
footprint CAP-0603 (0603 (1608M) Capacitor)
pins: 1, 2

## TCC0603X7R301K500CT
designator C?  Capacitance: 300pF  (hidden comment: *)
Capacitor, Ceramic (MLCC), 300pF, ±10%, 50V, X7R, ±10%, SMD 0603; Manufacturer: CCTC; Manufacturer Part Number: TCC0603X7R301K500CT
footprint CAP-0603 (0603 (1608M) Capacitor)
pins: 1, 2

## TCC0603X7R331K500CT
designator C?  Capacitance: 330pF  (hidden comment: *)
Capacitor, Ceramic (MLCC), 330pF, ±10%, 50V, X7R, ±10%, SMD 0603; Manufacturer: CCTC; Manufacturer Part Number: TCC0603X7R331K500CT
footprint CAP-0603 (0603 (1608M) Capacitor)
pins: 1, 2

## TCC0603X7R332K500CT
designator C?  Capacitance: 3.3nF  (hidden comment: *)
Capacitor, Ceramic (MLCC), 3.3nF, ±10%, 50V, X7R, ±10%, SMD 0603; Manufacturer: CCTC; Manufacturer Part Number: TCC0603X7R332K500CT
footprint CAP-0603 (0603 (1608M) Capacitor)
pins: 1, 2

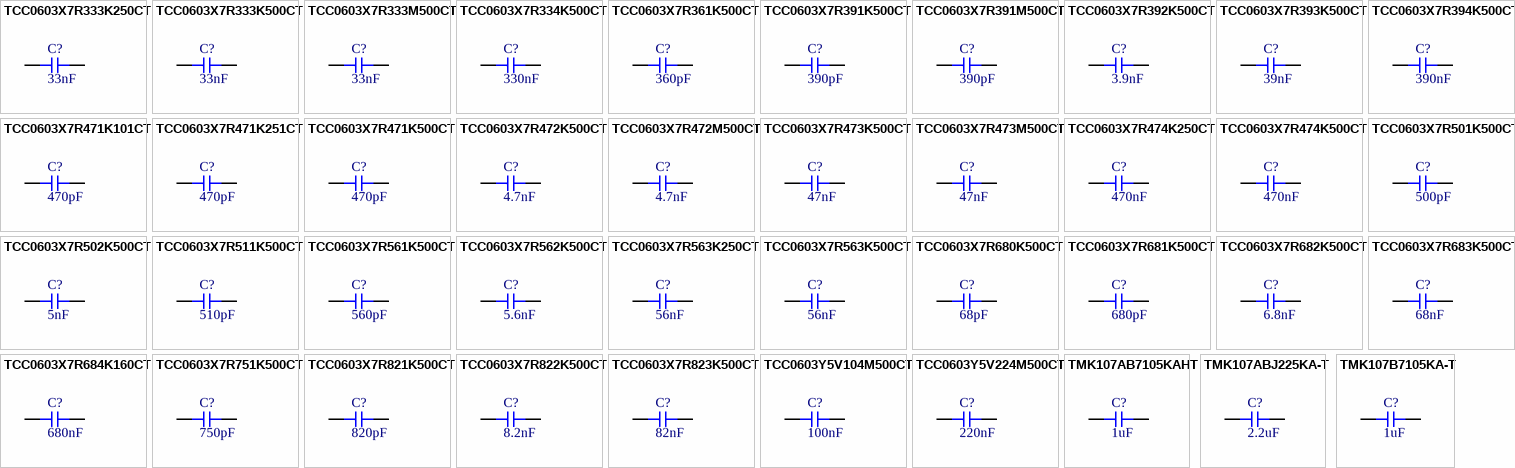
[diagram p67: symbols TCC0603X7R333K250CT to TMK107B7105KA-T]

## TCC0603X7R333K250CT
designator C?  Capacitance: 33nF  (hidden comment: *)
Capacitor, Ceramic (MLCC), 33nF, ±10%, 25V, X7R, ±10%, SMD 0603; Manufacturer: CCTC; Manufacturer Part Number: TCC0603X7R333K250CT
footprint CAP-0603 (0603 (1608M) Capacitor)
pins: 1, 2

## TCC0603X7R333K500CT
designator C?  Capacitance: 33nF  (hidden comment: *)
Capacitor, Ceramic (MLCC), 33nF, ±10%, 50V, X7R, ±10%, SMD 0603; Manufacturer: CCTC; Manufacturer Part Number: TCC0603X7R333K500CT
footprint CAP-0603 (0603 (1608M) Capacitor)
pins: 1, 2

## TCC0603X7R333M500CT
designator C?  Capacitance: 33nF  (hidden comment: *)
Capacitor, Ceramic (MLCC), 33nF, ±20%, 50V, X7R, ±20%, SMD 0603; Manufacturer: CCTC; Manufacturer Part Number: TCC0603X7R333M500CT
footprint CAP-0603 (0603 (1608M) Capacitor)
pins: 1, 2

## TCC0603X7R334K500CT
designator C?  Capacitance: 330nF  (hidden comment: *)
Capacitor, Ceramic (MLCC), 330nF, ±10%, 50V, X7R, ±10%, SMD 0603; Manufacturer: CCTC; Manufacturer Part Number: TCC0603X7R334K500CT
footprint CAP-0603 (0603 (1608M) Capacitor)
pins: 1, 2

## TCC0603X7R361K500CT
designator C?  Capacitance: 360pF  (hidden comment: *)
Capacitor, Ceramic (MLCC), 360pF, ±10%, 50V, X7R, ±10%, SMD 0603; Manufacturer: CCTC; Manufacturer Part Number: TCC0603X7R361K500CT
footprint CAP-0603 (0603 (1608M) Capacitor)
pins: 1, 2

## TCC0603X7R391K500CT
designator C?  Capacitance: 390pF  (hidden comment: *)
Capacitor, Ceramic (MLCC), 390pF, ±10%, 50V, X7R, ±10%, SMD 0603; Manufacturer: CCTC; Manufacturer Part Number: TCC0603X7R391K500CT
footprint CAP-0603 (0603 (1608M) Capacitor)
pins: 1, 2

## TCC0603X7R391M500CT
designator C?  Capacitance: 390pF  (hidden comment: *)
Capacitor, Ceramic (MLCC), 390pF, ±20%, 50V, X7R, ±20%, SMD 0603; Manufacturer: CCTC; Manufacturer Part Number: TCC0603X7R391M500CT
footprint CAP-0603 (0603 (1608M) Capacitor)
pins: 1, 2

## TCC0603X7R392K500CT
designator C?  Capacitance: 3.9nF  (hidden comment: *)
Capacitor, Ceramic (MLCC), 3.9nF, ±10%, 50V, X7R, ±10%, SMD 0603; Manufacturer: CCTC; Manufacturer Part Number: TCC0603X7R392K500CT
footprint CAP-0603 (0603 (1608M) Capacitor)
pins: 1, 2

## TCC0603X7R393K500CT
designator C?  Capacitance: 39nF  (hidden comment: *)
Capacitor, Ceramic (MLCC), 39nF, ±10%, 50V, X7R, ±10%, SMD 0603; Manufacturer: CCTC; Manufacturer Part Number: TCC0603X7R393K500CT
footprint CAP-0603 (0603 (1608M) Capacitor)
pins: 1, 2

## TCC0603X7R394K500CT
designator C?  Capacitance: 390nF  (hidden comment: *)
Capacitor, Ceramic (MLCC), 390nF, ±10%, 50V, X7R, ±10%, SMD 0603; Manufacturer: CCTC; Manufacturer Part Number: TCC0603X7R394K500CT
footprint CAP-0603 (0603 (1608M) Capacitor)
pins: 1, 2

## TCC0603X7R471K101CT
designator C?  Capacitance: 470pF  (hidden comment: *)
Capacitor, Ceramic (MLCC), 470pF, ±10%, 100V, X7R, ±10%, SMD 0603; Manufacturer: CCTC; Manufacturer Part Number: TCC0603X7R471K101CT
footprint CAP-0603 (0603 (1608M) Capacitor)
pins: 1, 2

## TCC0603X7R471K251CT
designator C?  Capacitance: 470pF  (hidden comment: *)
Capacitor, Ceramic (MLCC), 470pF, ±10%, 250V, X7R, ±10%, SMD 0603; Manufacturer: CCTC; Manufacturer Part Number: TCC0603X7R471K251CT
footprint CAP-0603 (0603 (1608M) Capacitor)
pins: 1, 2

## TCC0603X7R471K500CT
designator C?  Capacitance: 470pF  (hidden comment: *)
Capacitor, Ceramic (MLCC), 470pF, ±10%, 50V, X7R, ±10%, SMD 0603; Manufacturer: CCTC; Manufacturer Part Number: TCC0603X7R471K500CT
footprint CAP-0603 (0603 (1608M) Capacitor)
pins: 1, 2

## TCC0603X7R472K500CT
designator C?  Capacitance: 4.7nF  (hidden comment: *)
Capacitor, Ceramic (MLCC), 4.7nF, ±10%, 50V, X7R, ±10%, SMD 0603; Manufacturer: CCTC; Manufacturer Part Number: TCC0603X7R472K500CT
footprint CAP-0603 (0603 (1608M) Capacitor)
pins: 1, 2

## TCC0603X7R472M500CT
designator C?  Capacitance: 4.7nF  (hidden comment: *)
Capacitor, Ceramic (MLCC), 4.7nF, ±20%, 50V, X7R, ±20%, SMD 0603; Manufacturer: CCTC; Manufacturer Part Number: TCC0603X7R472M500CT
footprint CAP-0603 (0603 (1608M) Capacitor)
pins: 1, 2

## TCC0603X7R473K500CT
designator C?  Capacitance: 47nF  (hidden comment: *)
Capacitor, Ceramic (MLCC), 47nF, ±10%, 50V, X7R, ±10%, SMD 0603; Manufacturer: CCTC; Manufacturer Part Number: TCC0603X7R473K500CT
footprint CAP-0603 (0603 (1608M) Capacitor)
pins: 1, 2

## TCC0603X7R473M500CT
designator C?  Capacitance: 47nF  (hidden comment: *)
Capacitor, Ceramic (MLCC), 47nF, ±20%, 50V, X7R, ±20%, SMD 0603; Manufacturer: CCTC; Manufacturer Part Number: TCC0603X7R473M500CT
footprint CAP-0603 (0603 (1608M) Capacitor)
pins: 1, 2

## TCC0603X7R474K250CT
designator C?  Capacitance: 470nF  (hidden comment: *)
Capacitor, Ceramic (MLCC), 470nF, ±10%, 25V, X7R, ±10%, SMD 0603; Manufacturer: CCTC; Manufacturer Part Number: TCC0603X7R474K250CT
footprint CAP-0603 (0603 (1608M) Capacitor)
pins: 1, 2

## TCC0603X7R474K500CT
designator C?  Capacitance: 470nF  (hidden comment: *)
Capacitor, Ceramic (MLCC), 470nF, ±10%, 50V, X7R, ±10%, SMD 0603; Manufacturer: CCTC; Manufacturer Part Number: TCC0603X7R474K500CT
footprint CAP-0603 (0603 (1608M) Capacitor)
pins: 1, 2

## TCC0603X7R501K500CT
designator C?  Capacitance: 500pF  (hidden comment: *)
Capacitor, Ceramic (MLCC), 500pF, ±10%, 50V, X7R, ±10%, SMD 0603; Manufacturer: CCTC; Manufacturer Part Number: TCC0603X7R501K500CT
footprint CAP-0603 (0603 (1608M) Capacitor)
pins: 1, 2

## TCC0603X7R502K500CT
designator C?  Capacitance: 5nF  (hidden comment: *)
Capacitor, Ceramic (MLCC), 5nF, ±10%, 50V, X7R, ±10%, SMD 0603; Manufacturer: CCTC; Manufacturer Part Number: TCC0603X7R502K500CT
footprint CAP-0603 (0603 (1608M) Capacitor)
pins: 1, 2

## TCC0603X7R511K500CT
designator C?  Capacitance: 510pF  (hidden comment: *)
Capacitor, Ceramic (MLCC), 510pF, ±10%, 50V, X7R, ±10%, SMD 0603; Manufacturer: CCTC; Manufacturer Part Number: TCC0603X7R511K500CT
footprint CAP-0603 (0603 (1608M) Capacitor)
pins: 1, 2

## TCC0603X7R561K500CT
designator C?  Capacitance: 560pF  (hidden comment: *)
Capacitor, Ceramic (MLCC), 560pF, ±10%, 50V, X7R, ±10%, SMD 0603; Manufacturer: CCTC; Manufacturer Part Number: TCC0603X7R561K500CT
footprint CAP-0603 (0603 (1608M) Capacitor)
pins: 1, 2

## TCC0603X7R562K500CT
designator C?  Capacitance: 5.6nF  (hidden comment: *)
Capacitor, Ceramic (MLCC), 5.6nF, ±10%, 50V, X7R, ±10%, SMD 0603; Manufacturer: CCTC; Manufacturer Part Number: TCC0603X7R562K500CT
footprint CAP-0603 (0603 (1608M) Capacitor)
pins: 1, 2

## TCC0603X7R563K250CT
designator C?  Capacitance: 56nF  (hidden comment: *)
Capacitor, Ceramic (MLCC), 56nF, ±10%, 25V, X7R, ±10%, SMD 0603; Manufacturer: CCTC; Manufacturer Part Number: TCC0603X7R563K250CT
footprint CAP-0603 (0603 (1608M) Capacitor)
pins: 1, 2

## TCC0603X7R563K500CT
designator C?  Capacitance: 56nF  (hidden comment: *)
Capacitor, Ceramic (MLCC), 56nF, ±10%, 50V, X7R, ±10%, SMD 0603; Manufacturer: CCTC; Manufacturer Part Number: TCC0603X7R563K500CT
footprint CAP-0603 (0603 (1608M) Capacitor)
pins: 1, 2

## TCC0603X7R680K500CT
designator C?  Capacitance: 68pF  (hidden comment: *)
Capacitor, Ceramic (MLCC), 68pF, ±10%, 50V, X7R, ±10%, SMD 0603; Manufacturer: CCTC; Manufacturer Part Number: TCC0603X7R680K500CT
footprint CAP-0603 (0603 (1608M) Capacitor)
pins: 1, 2

## TCC0603X7R681K500CT
designator C?  Capacitance: 680pF  (hidden comment: *)
Capacitor, Ceramic (MLCC), 680pF, ±10%, 50V, X7R, ±10%, SMD 0603; Manufacturer: CCTC; Manufacturer Part Number: TCC0603X7R681K500CT
footprint CAP-0603 (0603 (1608M) Capacitor)
pins: 1, 2

## TCC0603X7R682K500CT
designator C?  Capacitance: 6.8nF  (hidden comment: *)
Capacitor, Ceramic (MLCC), 6.8nF, ±10%, 50V, X7R, ±10%, SMD 0603; Manufacturer: CCTC; Manufacturer Part Number: TCC0603X7R682K500CT
footprint CAP-0603 (0603 (1608M) Capacitor)
pins: 1, 2

## TCC0603X7R683K500CT
designator C?  Capacitance: 68nF  (hidden comment: *)
Capacitor, Ceramic (MLCC), 68nF, ±10%, 50V, X7R, ±10%, SMD 0603; Manufacturer: CCTC; Manufacturer Part Number: TCC0603X7R683K500CT
footprint CAP-0603 (0603 (1608M) Capacitor)
pins: 1, 2

## TCC0603X7R684K160CT
designator C?  Capacitance: 680nF  (hidden comment: *)
Capacitor, Ceramic (MLCC), 680nF, ±10%, 16V, X7R, ±10%, SMD 0603; Manufacturer: CCTC; Manufacturer Part Number: TCC0603X7R684K160CT
footprint CAP-0603 (0603 (1608M) Capacitor)
pins: 1, 2

## TCC0603X7R751K500CT
designator C?  Capacitance: 750pF  (hidden comment: *)
Capacitor, Ceramic (MLCC), 750pF, ±10%, 50V, X7R, ±10%, SMD 0603; Manufacturer: CCTC; Manufacturer Part Number: TCC0603X7R751K500CT
footprint CAP-0603 (0603 (1608M) Capacitor)
pins: 1, 2

## TCC0603X7R821K500CT
designator C?  Capacitance: 820pF  (hidden comment: *)
Capacitor, Ceramic (MLCC), 820pF, ±10%, 50V, X7R, ±10%, SMD 0603; Manufacturer: CCTC; Manufacturer Part Number: TCC0603X7R821K500CT
footprint CAP-0603 (0603 (1608M) Capacitor)
pins: 1, 2

## TCC0603X7R822K500CT
designator C?  Capacitance: 8.2nF  (hidden comment: *)
Capacitor, Ceramic (MLCC), 8.2nF, ±10%, 50V, X7R, ±10%, SMD 0603; Manufacturer: CCTC; Manufacturer Part Number: TCC0603X7R822K500CT
footprint CAP-0603 (0603 (1608M) Capacitor)
pins: 1, 2

## TCC0603X7R823K500CT
designator C?  Capacitance: 82nF  (hidden comment: *)
Capacitor, Ceramic (MLCC), 82nF, ±10%, 50V, X7R, ±10%, SMD 0603; Manufacturer: CCTC; Manufacturer Part Number: TCC0603X7R823K500CT
footprint CAP-0603 (0603 (1608M) Capacitor)
pins: 1, 2

## TCC0603Y5V104M500CT
designator C?  Capacitance: 100nF  (hidden comment: *)
Capacitor, Ceramic (MLCC), 100nF, ±20%, 50V, Y5V, ±20%, SMD 0603; Manufacturer: CCTC; Manufacturer Part Number: TCC0603Y5V104M500CT
footprint CAP-0603 (0603 (1608M) Capacitor)
pins: 1, 2

## TCC0603Y5V224M500CT
designator C?  Capacitance: 220nF  (hidden comment: *)
Capacitor, Ceramic (MLCC), 220nF, ±20%, 50V, Y5V, ±20%, SMD 0603; Manufacturer: CCTC; Manufacturer Part Number: TCC0603Y5V224M500CT
footprint CAP-0603 (0603 (1608M) Capacitor)
pins: 1, 2

## TMK107AB7105KAHT
designator C?  Capacitance: 1uF  (hidden comment: *)
Capacitor, Ceramic (MLCC), 1uF, ±10%, 25V, X7R, ±10%, SMD 0603; Manufacturer: Taiyo Yuden; Manufacturer Part Number: TMK107AB7105KAHT
footprint CAP-0603 (0603 (1608M) Capacitor)
pins: 1, 2

## TMK107ABJ225KA-T
designator C?  Capacitance: 2.2uF  (hidden comment: *)
Capacitor, Ceramic (MLCC), 2.2uF, ±10%, 25V, X5R, ±10%, SMD 0603; Manufacturer: Taiyo Yuden; Manufacturer Part Number: TMK107ABJ225KA-T
footprint CAP-0603 (0603 (1608M) Capacitor)
pins: 1, 2

## TMK107B7105KA-T
designator C?  Capacitance: 1uF  (hidden comment: *)
Capacitor, Ceramic (MLCC), 1uF, ±10%, 25V, X7R, ±10%, SMD 0603; Manufacturer: Taiyo Yuden; Manufacturer Part Number: TMK107B7105KA-T
footprint CAP-0603 (0603 (1608M) Capacitor)
pins: 1, 2

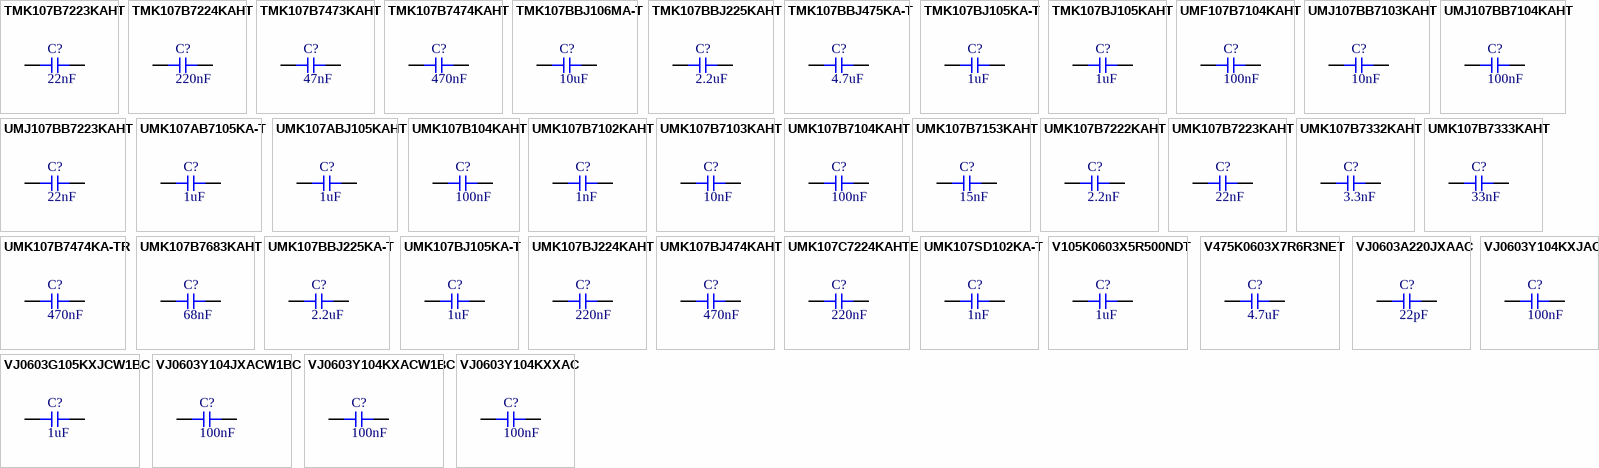
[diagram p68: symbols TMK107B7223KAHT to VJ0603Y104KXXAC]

## TMK107B7223KAHT
designator C?  Capacitance: 22nF  (hidden comment: *)
Capacitor, Ceramic (MLCC), 22nF, ±10%, 25V, X7R, ±10%, SMD 0603; Manufacturer: Taiyo Yuden; Manufacturer Part Number: TMK107B7223KAHT
footprint CAP-0603 (0603 (1608M) Capacitor)
pins: 1, 2

## TMK107B7224KAHT
designator C?  Capacitance: 220nF  (hidden comment: *)
Capacitor, Ceramic (MLCC), 220nF, ±10%, 25V, X7R, ±10%, SMD 0603; Manufacturer: Taiyo Yuden; Manufacturer Part Number: TMK107B7224KAHT
footprint CAP-0603 (0603 (1608M) Capacitor)
pins: 1, 2

## TMK107B7473KAHT
designator C?  Capacitance: 47nF  (hidden comment: *)
Capacitor, Ceramic (MLCC), 47nF, ±10%, 25V, X7R, ±10%, SMD 0603; Manufacturer: Taiyo Yuden; Manufacturer Part Number: TMK107B7473KAHT
footprint CAP-0603 (0603 (1608M) Capacitor)
pins: 1, 2

## TMK107B7474KAHT
designator C?  Capacitance: 470nF  (hidden comment: *)
Capacitor, Ceramic (MLCC), 470nF, ±10%, 25V, X7R, ±10%, SMD 0603; Manufacturer: Taiyo Yuden; Manufacturer Part Number: TMK107B7474KAHT
footprint CAP-0603 (0603 (1608M) Capacitor)
pins: 1, 2

## TMK107BBJ106MA-T
designator C?  Capacitance: 10uF  (hidden comment: *)
Capacitor, Ceramic (MLCC), 10uF, ±20%, 25V, X5R, ±20%, SMD 0603; Manufacturer: Taiyo Yuden; Manufacturer Part Number: TMK107BBJ106MA-T
footprint CAP-0603 (0603 (1608M) Capacitor)
pins: 1, 2

## TMK107BBJ225KAHT
designator C?  Capacitance: 2.2uF  (hidden comment: *)
Capacitor, Ceramic (MLCC), 2.2uF, ±10%, 25V, X5R, ±10%, SMD 0603; Manufacturer: Taiyo Yuden; Manufacturer Part Number: TMK107BBJ225KAHT
footprint CAP-0603 (0603 (1608M) Capacitor)
pins: 1, 2

## TMK107BBJ475KA-T
designator C?  Capacitance: 4.7uF  (hidden comment: *)
Capacitor, Ceramic (MLCC), 4.7uF, ±10%, 25V, X5R, ±10%, SMD 0603; Manufacturer: Taiyo Yuden; Manufacturer Part Number: TMK107BBJ475KA-T
footprint CAP-0603 (0603 (1608M) Capacitor)
pins: 1, 2

## TMK107BJ105KA-T
designator C?  Capacitance: 1uF  (hidden comment: *)
Capacitor, Ceramic (MLCC), 1uF, ±10%, 25V, X5R, ±10%, SMD 0603; Manufacturer: Taiyo Yuden; Manufacturer Part Number: TMK107BJ105KA-T
footprint CAP-0603 (0603 (1608M) Capacitor)
pins: 1, 2

## TMK107BJ105KAHT
designator C?  Capacitance: 1uF  (hidden comment: *)
Capacitor, Ceramic (MLCC), 1uF, ±10%, 25V, X5R, ±10%, SMD 0603; Manufacturer: Taiyo Yuden; Manufacturer Part Number: TMK107BJ105KAHT
footprint CAP-0603 (0603 (1608M) Capacitor)
pins: 1, 2

## UMF107B7104KAHT
designator C?  Capacitance: 100nF  (hidden comment: *)
Capacitor, Ceramic (MLCC), 100nF, ±10%, 50V, X7R, ±10%, SMD 0603; Manufacturer: Taiyo Yuden; Manufacturer Part Number: UMF107B7104KAHT
footprint CAP-0603 (0603 (1608M) Capacitor)
pins: 1, 2

## UMJ107BB7103KAHT
designator C?  Capacitance: 10nF  (hidden comment: *)
Capacitor, Ceramic (MLCC), 10nF, ±10%, 50V, X7R, ±10%, SMD 0603; Manufacturer: Taiyo Yuden; Manufacturer Part Number: UMJ107BB7103KAHT
footprint CAP-0603 (0603 (1608M) Capacitor)
pins: 1, 2

## UMJ107BB7104KAHT
designator C?  Capacitance: 100nF  (hidden comment: *)
Capacitor, Ceramic (MLCC), 100nF, ±10%, 50V, X7R, ±10%, SMD 0603; Manufacturer: Taiyo Yuden; Manufacturer Part Number: UMJ107BB7104KAHT
footprint CAP-0603 (0603 (1608M) Capacitor)
pins: 1, 2

## UMJ107BB7223KAHT
designator C?  Capacitance: 22nF  (hidden comment: *)
Capacitor, Ceramic (MLCC), 22nF, ±10%, 50V, X7R, ±10%, SMD 0603; Manufacturer: Taiyo Yuden; Manufacturer Part Number: UMJ107BB7223KAHT
footprint CAP-0603 (0603 (1608M) Capacitor)
pins: 1, 2

## UMK107AB7105KA-T
designator C?  Capacitance: 1uF  (hidden comment: *)
Capacitor, Ceramic (MLCC), 1uF, ±10%, 50V, X7R, ±10%, SMD 0603; Manufacturer: Taiyo Yuden; Manufacturer Part Number: UMK107AB7105KA-T
footprint CAP-0603 (0603 (1608M) Capacitor)
pins: 1, 2

## UMK107ABJ105KAHT
designator C?  Capacitance: 1uF  (hidden comment: *)
Capacitor, Ceramic (MLCC), 1uF, ±10%, 50V, X5R, ±10%, SMD 0603; Manufacturer: Taiyo Yuden; Manufacturer Part Number: UMK107ABJ105KAHT
footprint CAP-0603 (0603 (1608M) Capacitor)
pins: 1, 2

## UMK107B104KAHT
designator C?  Capacitance: 100nF  (hidden comment: *)
Capacitor, Ceramic (MLCC), 100nF, ±10%, 50V, X5R, ±10%, SMD 0603; Manufacturer: Taiyo Yuden; Manufacturer Part Number: UMK107B104KAHT
footprint CAP-0603 (0603 (1608M) Capacitor)
pins: 1, 2

## UMK107B7102KAHT
designator C?  Capacitance: 1nF  (hidden comment: *)
Capacitor, Ceramic (MLCC), 1nF, ±10%, 50V, X7R, ±10%, SMD 0603; Manufacturer: Taiyo Yuden; Manufacturer Part Number: UMK107B7102KAHT
footprint CAP-0603 (0603 (1608M) Capacitor)
pins: 1, 2

## UMK107B7103KAHT
designator C?  Capacitance: 10nF  (hidden comment: *)
Capacitor, Ceramic (MLCC), 10nF, ±10%, 50V, X7R, ±10%, SMD 0603; Manufacturer: Taiyo Yuden; Manufacturer Part Number: UMK107B7103KAHT
footprint CAP-0603 (0603 (1608M) Capacitor)
pins: 1, 2

## UMK107B7104KAHT
designator C?  Capacitance: 100nF  (hidden comment: *)
Capacitor, Ceramic (MLCC), 100nF, ±10%, 50V, X7R, ±10%, SMD 0603; Manufacturer: Taiyo Yuden; Manufacturer Part Number: UMK107B7104KAHT
footprint CAP-0603 (0603 (1608M) Capacitor)
pins: 1, 2

## UMK107B7153KAHT
designator C?  Capacitance: 15nF  (hidden comment: *)
Capacitor, Ceramic (MLCC), 15nF, ±10%, 50V, X7R, ±10%, SMD 0603; Manufacturer: Taiyo Yuden; Manufacturer Part Number: UMK107B7153KAHT
footprint CAP-0603 (0603 (1608M) Capacitor)
pins: 1, 2

## UMK107B7222KAHT
designator C?  Capacitance: 2.2nF  (hidden comment: *)
Capacitor, Ceramic (MLCC), 2.2nF, ±10%, 50V, X7R, ±10%, SMD 0603; Manufacturer: Taiyo Yuden; Manufacturer Part Number: UMK107B7222KAHT
footprint CAP-0603 (0603 (1608M) Capacitor)
pins: 1, 2

## UMK107B7223KAHT
designator C?  Capacitance: 22nF  (hidden comment: *)
Capacitor, Ceramic (MLCC), 22nF, ±10%, 50V, X7R, ±10%, SMD 0603; Manufacturer: Taiyo Yuden; Manufacturer Part Number: UMK107B7223KAHT
footprint CAP-0603 (0603 (1608M) Capacitor)
pins: 1, 2

## UMK107B7332KAHT
designator C?  Capacitance: 3.3nF  (hidden comment: *)
Capacitor, Ceramic (MLCC), 3.3nF, ±10%, 50V, X7R, ±10%, SMD 0603; Manufacturer: Taiyo Yuden; Manufacturer Part Number: UMK107B7332KAHT
footprint CAP-0603 (0603 (1608M) Capacitor)
pins: 1, 2

## UMK107B7333KAHT
designator C?  Capacitance: 33nF  (hidden comment: *)
Capacitor, Ceramic (MLCC), 33nF, ±10%, 50V, X7R, ±10%, SMD 0603; Manufacturer: Taiyo Yuden; Manufacturer Part Number: UMK107B7333KAHT
footprint CAP-0603 (0603 (1608M) Capacitor)
pins: 1, 2

## UMK107B7474KA-TR
designator C?  Capacitance: 470nF  (hidden comment: *)
Capacitor, Ceramic (MLCC), 470nF, ±10%, 50V, X7R, ±10%, SMD 0603; Manufacturer: Taiyo Yuden; Manufacturer Part Number: UMK107B7474KA-TR
footprint CAP-0603 (0603 (1608M) Capacitor)
pins: 1, 2

## UMK107B7683KAHT
designator C?  Capacitance: 68nF  (hidden comment: *)
Capacitor, Ceramic (MLCC), 68nF, ±10%, 50V, X7R, ±10%, SMD 0603; Manufacturer: Taiyo Yuden; Manufacturer Part Number: UMK107B7683KAHT
footprint CAP-0603 (0603 (1608M) Capacitor)
pins: 1, 2

## UMK107BBJ225KA-T
designator C?  Capacitance: 2.2uF  (hidden comment: *)
Capacitor, Ceramic (MLCC), 2.2uF, ±10%, 50V, X5R, ±10%, SMD 0603; Manufacturer: Taiyo Yuden; Manufacturer Part Number: UMK107BBJ225KA-T
footprint CAP-0603 (0603 (1608M) Capacitor)
pins: 1, 2

## UMK107BJ105KA-T
designator C?  Capacitance: 1uF  (hidden comment: *)
Capacitor, Ceramic (MLCC), 1uF, ±10%, 50V, X5R, ±10%, SMD 0603; Manufacturer: Taiyo Yuden; Manufacturer Part Number: UMK107BJ105KA-T
footprint CAP-0603 (0603 (1608M) Capacitor)
pins: 1, 2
